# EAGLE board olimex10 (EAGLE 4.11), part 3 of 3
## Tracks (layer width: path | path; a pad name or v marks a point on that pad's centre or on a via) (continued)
N$64 (continued)
  Top 0.254: IC2.1 40.64,135.89 39.37,134.62 39.37,130.81 40.64,129.54 47.62,129.54 47.62,131.44 SW2.13
N$65
  Top 0.254: SW2.11 49.53,135.89 49.53,138.43 45.72,142.24 IC2.14
N$66
  Top 0.254: SW2.10 57.78,130.18 59.69,130.18 59.69,133.35 57.15,135.89 57.15,138.43 52.07,143.51 52.07,146.69 49.53,149.22 48.26,149.22 IC2.13
N$67
  Top 0.254: SW2.9 54.61,135.89 54.61,139.7 50.8,143.51 IC2.12
N$68
  Top 0.254: SW3.16 70.48,130.18 74.93,130.18 74.93,133.35 76.2,134.62 IC3.4
N$69
  Top 0.254: SW3.15 71.12,133.35 73.66,135.89 IC3.3
N$70
  Top 0.254: SW3.14 73.66,133.35 74.93,134.62 74.93,138.43 74.3,139.06 71.12,139.06 IC3.2
N$71
  Top 0.254: IC3.1 68.58,135.89 67.31,134.62 67.31,130.81 68.58,129.54 75.56,129.54 75.56,131.44 SW3.13
N$72
  Top 0.254: SW3.11 81.28,133.35 82.55,134.62 82.55,146.05 78.74,149.86 69.85,149.86 69.85,143.51 70.48,142.88 73.03,142.88 73.03,144.15 IC3.14
N$73
  Top 0.254: SW3.10 81.92,130.18 77.47,130.18 77.47,142.24 76.2,143.51 IC3.13
N$74  (via drill 0.61)
  Top 0.254: v87.63,142.24 87.63,134.62 86.36,133.35 SW3.9
  Bottom 0.254: v87.63,142.24 87,142.88 80.64,142.88 IC3.12
N$75
  Top 0.254: SW4.16 98.42,130.18 102.87,130.18 102.87,133.35 104.14,134.62 IC4.4
N$76
  Top 0.254: SW4.15 99.06,133.35 101.6,135.89 IC4.3
N$77
  Top 0.254: SW4.14 101.6,133.35 102.87,134.62 102.87,138.43 102.23,139.06 99.06,139.06 IC4.2
N$78
  Top 0.254: IC4.1 96.52,135.89 95.25,134.62 95.25,130.81 96.52,129.54 103.5,129.54 103.5,131.44 SW4.13
N$79  (via drill 0.61)
  Top 0.254: v97.79,133.99 97.79,139.7 101.6,143.51 IC4.14
  Bottom 0.254: v97.79,133.99 107.31,133.99 SW4.11
N$80
  Top 0.254: SW4.10 108.58,135.25 105.41,135.25 105.41,142.24 104.14,143.51 IC4.13
N$81
  Top 0.254: SW4.9 110.49,135.89 110.49,139.7 106.68,143.51 IC4.12
N$82
  Top 0.254: SW4.12 106.68,130.81 103.5,127.64 94.61,127.64 94.61,137.16 95.25,137.79 95.25,139.7 99.06,143.51 IC4.15
N$83
  Top 0.254: SW3.12 78.74,133.35 80.01,134.62 80.01,146.69 77.47,149.22 71.12,149.22 IC3.15
N$84
  Top 0.254: SW2.12 50.8,130.81 47.62,127.64 38.73,127.64 38.73,137.16 39.37,137.79 39.37,139.7 43.18,143.51 IC2.15
N$85
  Top 0.254: R16.1 246.38,191.13 247.65,192.41 248.92,192.41 DEA0.A
N$86
  Bottom 0.254: R17.1 8.26,182.88 10.79,180.34 DMA00.A
N$87
  Bottom 0.254: R18.1 23.5,182.88 26.04,180.34 DMA01.A
N$88
  Bottom 0.254: R19.1 38.73,182.88 41.27,180.34 DMA02.A
N$89
  Bottom 0.254: R20.1 76.83,182.88 79.38,180.34 DMA03.A
N$90
  Bottom 0.254: R21.1 92.08,182.88 94.61,180.34 DMA04.A
N$91
  Bottom 0.254: R22.1 107.31,182.88 109.86,180.34 DMA05.A
N$92
  Bottom 0.254: R23.1 145.41,182.88 147.96,180.34 DMA06.A
N$93
  Bottom 0.254: R24.1 160.66,182.88 163.19,180.34 DMA07.A
N$94
  Bottom 0.254: R25.1 175.9,182.88 178.44,180.34 DMA08.A
N$95
  Bottom 0.254: R26.1 214,182.88 216.53,180.34 DMA09.A
N$96
  Top 0.254: R27.1 229.24,182.88 231.78,180.34 DMA10.A
N$97  (via drill 0.61)
  Top 0.254: v246.38,180.34 246.38,180.97 244.47,182.88 R28.1
  Bottom 0.254: v246.38,180.34 DMA11.A
N$98
  Bottom 0.254: R29.1 8.26,170.18 10.79,172.72 DMB00.A
N$99
  Bottom 0.254: R30.1 23.5,170.18 26.04,172.72 DMB01.A
N$100
  Bottom 0.254: R31.1 38.73,170.18 41.27,172.72 DMB02.A
N$101
  Bottom 0.254: R32.1 76.83,170.18 79.38,172.72 DMB03.A
N$102
  Bottom 0.254: R33.1 92.08,170.18 94.61,172.72 DMB04.A
N$103
  Bottom 0.254: R34.1 107.31,170.18 109.86,172.72 DMB05.A
N$104
  Bottom 0.254: R35.1 145.41,170.18 147.96,172.72 DMB06.A
N$105
  Bottom 0.254: R36.1 160.66,170.18 163.19,172.72 DMB07.A
N$106
  Bottom 0.254: R37.1 175.9,170.18 178.44,172.72 DMB08.A
N$107
  Bottom 0.254: R38.1 214,170.18 216.53,172.72 DMB09.A
N$108
  Bottom 0.254: R39.1 229.24,170.18 231.78,172.72 DMB10.A
N$109  (via drill 0.61)
  Top 0.254: R40.1 v243.84,172.72
  Bottom 0.254: v243.84,172.72 DMB11.A
N$110
  Top 0.254: CIE.A 12.7,165.74 10.16,168.28 R41.1
N$111
  Top 0.254: EIE.A 27.94,165.74 25.4,168.28 R42.1
N$112
  Top 0.254: PIE.A 43.18,165.74 40.64,168.28 R43.1
N$113
  Top 0.254: DRE.A 81.28,165.74 78.74,168.28 R44.1
N$114
  Top 0.254: R/W.A 96.52,165.74 93.98,168.28 R45.1
N$115
  Top 0.254: DBR.A 111.76,165.74 109.22,168.28 R46.1
N$116
  Top 0.254: DRL.A 149.86,165.74 147.32,168.28 R47.1
N$117
  Top 0.254: WLS.A 165.1,165.74 162.56,168.28 R48.1
N$118
  Top 0.254: NXD.A 180.34,165.74 177.8,168.28 R49.1
N$119
  Top 0.254: WCO.A 218.44,165.74 215.9,168.28 R50.1
N$120
  Top 0.254: PER.A 233.68,165.74 231.14,168.28 R51.1
N$121  (via drill 0.61)
  Top 0.254: DCF.A v248.92,169.54
  Bottom 0.254: v248.92,169.54 248.28,170.18 R52.1
N$122
  Bottom 0.254: F.3.K 15.24,181.61 14.61,181.61 13.97,180.97 13.97,178.44 56.52,178.44 IC47.2
N$123  (via drill 0.61)
  Top 0.254: v34.29,184.78 31.11,187.96 F.2.K
  Bottom 0.254: v34.29,184.78 34.92,184.15 59.69,184.15 IC47.4
N$124
  Bottom 0.254: F.1.K 46.35,187.96 48.26,189.87 71.75,189.87 72.39,189.23 72.39,182.25 70.48,182.25 IC47.6
N$125
  Bottom 0.254: DMA00.K 15.88,180.34 21.59,186.06 69.22,186.06 IC47.8
N$126
  Top 0.254: DMA01.K 31.11,180.34 43.18,192.41 66.04,192.41 IC47.10
N$127
  Top 0.254: DMA02.K 45.72,180.97 55.24,190.5 57.15,190.5 57.15,186.69 57.78,186.06 60.33,186.06 60.33,187.32 IC47.12
N$128
  Bottom 0.254: IC48.2 56.52,167 34.29,167 31.11,163.83 24.77,163.83 15.88,172.72 DMB00.K
N$129
  Top 0.254: DMB01.K 31.11,172.72 41.27,162.56 69.85,162.56 69.85,166.37 69.22,167 63.5,167 IC48.4
N$130
  Top 0.254: G2.+@1 G2.+ 292.74,18.41 292.74,19.05 G2.+@3 G2.+@4 | G2.+@4 G2.+@2 | D3.A 293.37,12.7 G2.+@4
N$131
  Top 0.254: G1.+@1 G1.+ 292.74,48.9 292.74,49.53 G1.+@3 G1.+@4 | G1.+@4 G1.+@2 | D2.A 293.37,43.18 G1.+@4
N$132
  Top 0.254: DMB02.K 45.72,172.09 44.45,170.81 44.45,164.47 45.72,163.19 67.94,163.19 67.94,164.47 IC48.6
N$133
  Bottom 0.254: CIE.K 15.24,171.45 14.61,171.45 13.97,172.09 13.97,174.62 69.22,174.62 IC48.8
N$134
  Bottom 0.254: EIE.K 31.11,165.1 34.92,168.91 62.23,168.91 IC48.10
N$135
  Top 0.254: PIE.K 54.61,165.1 54.61,166.37 IC48.12
N$136
  Bottom 0.254: DEA7.K 99.69,187.96 103.5,184.15 129.54,184.15 IC49.4
N$137  (via drill 0.61)
  Top 0.254: v132.72,186.06 IC49.6
  Bottom 0.254: v132.72,186.06 116.84,186.06 114.94,187.96 DEA6.K
N$138  (via drill 0.61)
  Top 0.254: v136.53,184.78 139.7,187.96 IC49.8
  Bottom 0.254: v136.53,184.78 113.03,184.78 108.58,189.23 78.11,189.23 78.11,186.69 83.82,180.97 DMA03.K
N$139  (via drill 0.61)
  Top 0.254: v109.22,189.87 99.69,180.34 DMA04.K
  Bottom 0.254: v109.22,189.87 110.49,191.13 132.72,191.13 IC49.10
N$140
  Top 0.254: DMA05.K 114.3,180.97 123.19,189.87 123.19,190.5 128.27,195.58 129.54,195.58 IC49.12
N$141  (via drill 0.61)
  Top 0.254: v125.73,174.62 125.73,167.64 127,166.37 IC50.2
  Bottom 0.254: v125.73,174.62 86.36,174.62 84.45,172.72 DMB03.K
N$142  (via drill 0.61)
  Top 0.254: v105.41,161.93 105.41,165.74 99.06,172.09 DMB04.K | v132.08,161.93 IC50.4
  Bottom 0.254: v105.41,161.93 v132.08,161.93
N$143  (via drill 0.61)
  Top 0.254: v118.11,169.54 114.94,172.72 DMB05.K | v135.89,169.54 135.89,168.91 137.16,167.64 IC50.6
  Bottom 0.254: v118.11,169.54 v135.89,169.54
N$144  (via drill 0.61)
  Top 0.254: v100.33,169.54 100.33,167 99.06,165.74 R/W.K
  Bottom 0.254: v100.33,169.54 100.97,168.91 114.94,168.91 117.47,171.45 123.19,171.45 123.83,170.81 132.72,170.81 IC50.10
N$145  (via drill 0.61)
  Top 0.254: v129.54,168.28 IC50.12
  Bottom 0.254: v129.54,168.28 118.11,168.28 114.94,165.1 DBR.K
N$146  (via drill 0.61)
  Top 0.254: v156.84,184.15 153.03,187.96 DEA5.K
  Bottom 0.254: v156.84,184.15 180.34,184.15 182.88,181.61 191.77,181.61 192.41,182.25 193.68,182.25 IC51.2
N$147  (via drill 0.61)
  Top 0.254: v173.99,175.9 173.99,180.97 167.64,187.32 DEA4.K | v200.03,175.9 200.66,176.53 IC51.4
  Bottom 0.254: v173.99,175.9 174.62,176.53 198.75,176.53 199.39,175.9 v200.03,175.9
N$148  (via drill 0.61)
  Top 0.254: v203.2,184.15 205.74,181.61 IC51.6
  Bottom 0.254: v203.2,184.15 202.56,184.78 198.12,184.78 197.49,184.15 187.32,184.15 183.51,187.96 DEA3.K
N$149  (via drill 0.61)
  Top 0.254: v190.5,179.07 191.13,179.71 v191.13,186.06
  Bottom 0.254: v190.5,179.07 154.31,179.07 153.03,180.34 DMA06.K | v191.13,186.06 206.38,186.06 IC51.8
N$150  (via drill 0.61)
  Top 0.254: v172.09,194.31 166.37,188.59 166.37,182.25 167.64,180.97 DMA07.K | v199.39,194.94 199.39,186.69 200.03,186.06 202.56,186.06 202.56,187.32 IC51.10
  Bottom 0.254: v172.09,194.31 173.35,195.58 198.75,195.58 v199.39,194.94
N$151  (via drill 0.61)
  Top 0.254: v184.78,183.51 184.78,182.88 182.88,180.97 DMA08.K | v198.12,183.51 IC51.12
  Bottom 0.254: v184.78,183.51 v198.12,183.51
N$152  (via drill 0.61)
  Top 0.254: v158.12,177.8 153.03,172.72 DMB06.K | v194.31,178.44 194.31,167.64 195.58,166.37 IC52.2
  Bottom 0.254: v158.12,177.8 193.68,177.8 v194.31,178.44
N$153  (via drill 0.61)
  Top 0.254: v177.16,163.83 168.28,172.72 DMB07.K
  Bottom 0.254: v177.16,163.83 177.8,163.19 198.75,163.19 IC52.4
N$154  (via drill 0.61)
  Top 0.254: v205.74,169.54 IC52.6
  Bottom 0.254: v205.74,169.54 187.32,169.54 183.51,172.72 DMB08.K
N$155  (via drill 0.61)
  Top 0.254: v169.54,170.18 169.54,167.64 167.64,165.74 WLS.K
  Bottom 0.254: v169.54,170.18 175.26,175.9 198.12,175.9 199.39,174.62 201.29,174.62 IC52.10
N$156  (via drill 0.61)
  Top 0.254: v187.32,173.99 187.32,170.18 182.88,165.74 NXD.K
  Bottom 0.254: v187.32,173.99 188.59,175.26 196.85,175.26 198.12,173.99 IC52.12
N$157  (via drill 0.61)
  Top 0.254: v222.88,182.88 222.88,185.42 220.98,187.32 DEA2.K
  Bottom 0.254: v222.88,182.88 224.16,181.61 257.18,181.61 257.81,180.97 259.71,180.97 260.99,182.25 262.25,182.25 IC53.2
N$158  (via drill 0.61)
  Top 0.254: v262.89,186.06 264.8,184.15 264.8,182.25 265.43,181.61 265.43,179.07 266.06,178.44 268.61,178.44 268.61,179.71 IC53.4
  Bottom 0.254: v262.89,186.06 260.99,186.06 259.71,187.32 258.44,187.32 257.81,186.69 238.12,186.69 236.85,187.96 DEA1.K
N$159  (via drill 0.61)
  Top 0.254: v257.81,182.25 252.09,187.96 DEA0.K
  Bottom 0.254: v257.81,182.25 258.44,182.88 265.43,182.88 266.06,182.25 272.42,182.25 IC53.6
N$160
  Top 0.254: DMA09.K 221.62,180.34 235.59,194.31 276.86,194.31 IC53.8
N$161  (via drill 0.61)
  Top 0.254: v236.85,184.78 236.85,181.61 236.22,180.97 DMA10.K | v258.44,186.06 260.35,187.96 260.35,189.23 263.52,192.41 271.78,192.41 IC53.10
  Bottom 0.254: v236.85,184.78 238.12,186.06 v258.44,186.06
N$162  (via drill 0.61)
  Top 0.254: v255.27,183.51 252.09,180.34 DMA11.K | v266.06,183.51 266.7,184.15 IC53.12
  Bottom 0.254: v255.27,183.51 v266.06,183.51
N$163
  Top 0.254: DMB09.K 226.69,172.72 227.33,172.09 234.31,179.07 237.49,179.07 237.49,183.51 238.76,184.78 241.3,184.78 241.3,170.18 240.66,169.54 240.66,149.86 243.21,147.32 243.21,144.15 265.43,144.15 265.43,162.56 264.16,163.83 IC54.2
N$164  (via drill 0.61)
  Top 0.254: v258.44,172.09 259.08,171.45 v259.08,166.37
  Bottom 0.254: v258.44,172.09 257.81,171.45 238.12,171.45 236.85,172.72 DMB10.K | v259.08,166.37 259.71,167 267.33,167 IC54.4
N$165  (via drill 0.61)
  Top 0.254: v252.73,169.54 252.73,170.81 251.46,172.09 DMB11.K | v273.69,169.54 274.32,168.91 IC54.6
  Bottom 0.254: v252.73,169.54 v273.69,169.54
N$166  (via drill 0.61)
  Top 0.254: v241.94,146.69 240.03,148.59 240.03,170.18 240.66,170.81 240.66,184.15 239.4,184.15 238.12,182.88 238.12,178.44 234.95,178.44 221.62,165.1 WCO.K | v274.32,147.32 275.59,148.59 275.59,169.54 276.86,170.81 IC54.8
  Bottom 0.254: v241.94,146.69 242.57,147.32 v274.32,147.32
N$167
  Top 0.254: PER.K 236.22,148.59 241.3,143.51 273.05,143.51 273.05,168.91 271.78,170.18 IC54.10
N$168  (via drill 0.61)
  Top 0.254: DCF.K v251.46,168.28
  Bottom 0.254: v251.46,168.28 273.69,168.28 274.95,169.54 274.95,170.18 274.32,170.18 273.69,170.81 268.61,170.81 IC54.12
N$169
  Top 0.254: PAD10.1 DRE.K
N$170
  Top 0.254: PAD11.1 DRL.K
N$171
  Bottom 0.254: DEA8.K 84.45,187.96 93.34,179.07 124.46,179.07 IC49.2
NXD  (via drill 0.61)  (1 unrouted)
  Top 0.254: v207.65,53.34 207.01,52.7 v207.01,6.99 | v118.75,4.45 116.84,6.35 IC23.5 | v190.5,161.29 190.5,170.81 v189.87,171.45 | v226.06,161.93 227.97,163.83 234.95,163.83 234.95,165.74 235.59,166.37 238.76,166.37 238.76,153.67 v238.12,153.03
  Bottom 0.254: IC23.5 114.3,10.16 74.93,10.16 74.3,10.79 53.98,10.79 52.07,8.89 34.92,8.89 33.66,7.62 SV1.17 | v207.01,6.99 205.74,5.71 153.67,5.71 153.03,6.35 137.16,6.35 135.89,5.08 119.38,5.08 v118.75,4.45 | v207.65,53.34 IC30.4 | v189.87,171.45 190.5,170.81 193.68,170.81 IC52.13 | v190.5,161.29 191.13,161.93 209.55,161.93 210.19,161.29 211.46,161.29 212.09,161.93 v226.06,161.93 | v238.12,153.03 241.94,149.22 262.25,149.22 263.52,151.13 SV3.17
NXD\  (via drill 0.61)
  Top 0.254: v134.62,71.75 134.62,65.41 130.18,60.96 130.18,52.7 129.54,52.07 129.54,39.37 130.18,38.73 130.18,24.13 127.64,21.59 127.64,5.08 121.92,5.08 IC23.6 | v146.05,73.03 147.32,74.3 147.32,109.22 148.59,110.49 148.59,135.89 150.5,137.79 150.5,140.34 v153.03,142.88
  Bottom 0.254: v134.62,71.75 135.89,73.03 v146.05,73.03 | v153.03,142.88 153.67,142.24 161.29,142.24 161.93,142.88 210.82,142.88 225.43,128.27 225.43,107.31 219.07,107.31 IC12.12
PBIT  (via drill 0.61)
  Top 0.254: v61.59,90.17 60.96,89.53 60.96,43.81 62.23,42.55 62.23,24.13 67.31,24.13 IC35.11 | v58.42,93.34 57.15,94.61 57.15,109.22 58.42,110.49 IC14.6
  Bottom 0.254: v61.59,90.17 v58.42,93.34
PCA
  Bottom 0.254: IC55.5 151.13,12.7 152.4,13.97 179.07,13.97 180.34,12.7 IC37.8 212.09,12.7 213.36,11.43 224.16,11.43 224.16,95.89 219.71,100.33 217.17,100.33 IC12.3
PER  (via drill 0.61)  (1 unrouted)
  Top 0.254: v204.47,64.77 204.47,129.54 203.2,130.81 203.2,138.43 191.13,150.5 143.51,150.5 143.51,134.62 142.24,133.35 IC9.9 | v34.29,31.75 34.29,23.5 36.83,20.95 36.83,9.53 38.1,8.26 SV1.21 | v166.37,37.47 168.91,34.92 v168.91,33.66 | IC54.11 269.24,171.45 267.97,170.18 267.97,153.03 269.24,151.76 SV3.21
  Bottom 0.254: v204.47,64.77 IC30.2 211.46,57.78 216.53,57.78 217.17,57.15 220.98,57.15 220.98,38.1 217.17,34.29 169.54,34.29 v168.91,33.66 | v34.29,31.75 36.83,34.29 127.64,34.29 129.54,36.2 149.86,36.2 151.13,37.47 v166.37,37.47
PER\  (via drill 0.61)
  Top 0.254: v146.05,102.87 146.05,129.54 144.78,130.81 IC9.8 | v157.48,102.87 160.02,105.41 v160.02,107.31
  Bottom 0.254: v157.48,102.87 v146.05,102.87 | v160.02,107.31 206.38,107.31 209.55,104.14 IC12.4
PIE  (via drill 0.61)  (1 unrouted)
  Top 0.254: v186.06,4.45 190.5,8.89 INTENB.2 | v153.03,5.08 151.76,6.35 | 151.76,6.35 151.76,13.34 IC55.4 | v221.62,8.26 221.62,50.16 IC30.17 | 151.76,6.35 151.76,1.91 101.6,1.91 98.42,5.08 98.42,9.53 93.34,9.53 92.71,8.89 92.71,1.91 24.13,1.91 18.41,7.62 SV1.5 | v62.23,178.44 62.23,177.8 58.42,173.99 IC48.13 | v158.75,175.9 166.37,168.28 166.37,164.47 174.62,156.21 234.31,156.21 v234.31,158.75 | v241.94,158.75 v241.94,154.94
  Bottom 0.254: v153.03,5.08 185.42,5.08 v186.06,4.45 217.81,4.45 v221.62,8.26 | v62.23,178.44 62.87,177.8 149.86,177.8 150.5,178.44 151.76,178.44 152.4,177.8 156.84,177.8 v158.75,175.9 | v234.31,158.75 v241.94,158.75 | v241.94,154.94 241.94,152.4 247.01,152.4 248.28,151.13 SV3.5
PROTECT  (via drill 0.61)
  Top 0.254: IC5.6 v142.24,140.97 | v162.56,140.97 IC6.3
  Bottom 0.254: v142.24,140.97 v162.56,140.97
SETNXD\
  Top 0.254: IC23.4 112.39,5.71 99.06,5.71 99.06,17.14 91.44,24.77 91.44,43.18 92.08,43.81 92.08,94.61 92.71,95.25 92.71,99.69 91.44,100.97 IC21.9
SETPER\
  Bottom 0.254: IC13.5 25.4,114.3 22.86,114.3 19.05,118.11 19.05,122.56 12.06,122.56 11.43,123.19 11.43,129.54 137.16,129.54 IC9.10
SETWLS\  (via drill 0.61)
  Top 0.254: v139.7,128.27 137.16,125.73 IC9.4 | v171.45,130.18 171.45,134.62 172.72,135.89 IC6.7
  Bottom 0.254: v139.7,128.27 140.97,129.54 160.02,129.54 160.66,130.18 v171.45,130.18
SKIP\  (via drill 0.61)
  Top 0.254: IC19.6 198.12,90.17 195.58,92.71 IC19.10 v195.58,104.14 | v132.08,104.78 IC17.2
  Bottom 0.254: R1.1 183.51,86.36 184.15,87 186.06,87 IC19.2 189.87,87 196.22,87 IC19.6 | v132.08,104.78 144.15,104.78 144.78,105.41 169.54,105.41 170.81,104.14 v195.58,104.14
START\  (via drill 0.61)
  Top 0.254: 144.15,45.09 144.15,14.61 DMA0-3.11 | 144.15,45.09 DMA4-7.11 | 144.15,45.09 144.15,79.38 DMA8-11.11 | v146.05,99.69 v146.05,81.28 | v162.56,100.33 IC18.3
  Bottom 0.254: v162.56,100.33 149.86,100.33 148.59,99.06 146.69,99.06 v146.05,99.69 | v146.05,81.28 DMA8-11.11
VCC  (via drill 0.61)  (3 unrouted)
  Top 0.508: J7.2 193.04,41.27 191.13,43.18 191.13,45.72 193.04,47.62 J5.2 J4.2 J3.2 | 187.96,29.21 v187.96,40.64 | 187.96,29.21 INTENB.16 | IC31.20 171.45,66.04 C31.1 | IC38.20 171.45,31.75 C38.1 | IC55.14 156.21,24.13 C40.1 156.21,26.04 155.57,26.67 v155.57,27.94 | 139.7,60.33 v139.06,59.69 | 139.7,60.33 139.7,61.59 140.34,62.23 C39.1 | 139.7,60.33 139.7,40.64 140.34,40.01 140.34,29.21 140.97,28.57 C46.1 | v186.69,29.21 187.96,29.21 | IC37.20 217.17,31.75 C37.1 | IC30.20 217.17,62.23 C30.1 216.53,63.5 216.53,87 FIELD.16 217.17,90.17 C44.1 217.17,92.08 216.53,92.71 216.53,109.86 IC12.14 217.17,113.03 C12.1 | IC17.16 129.54,120.65 128.27,121.92 128.27,128.91 127,130.18 C9.1 127,131.44 125.73,132.72 125.73,141.6 127,142.88 C5.1 | 153.67,128.91 154.94,130.18 C10.1 | 153.67,128.91 152.4,127.64 152.4,121.28 154.94,118.75 C18.1 154.94,117.47 155.57,116.84 155.57,114.3 156.21,113.67 C27.1 156.21,95.25 DAR8-11.16 154.94,91.44 154.94,64.14 156.21,62.87 C42.1 | 153.67,128.91 153.67,141.6 154.94,142.88 C6.1 | DMA8-11.16 140.97,95.25 C8.1 | IC24.20 171.45,100.33 C24.1 | IC19.14 C19.1 | IC11.4 193.04,113.03 195.58,115.57 IC11.10 | 181.61,120.02 181.61,128.91 180.34,130.18 C7.1 | 181.61,120.02 182.88,118.75 C11.1 | RA.1 RL.1 208.28,121.92 IC8.4 206.38,128.91 206.38,138.43 C45.+ | C48.1 220.98,130.18 219.71,131.44 219.71,132.08 IC8.8 | 181.61,120.02 181.61,98.42 182.88,97.16 R1.2 | 49.53,109.22 45.72,105.41 IC33.16 | 50.16,109.86 49.53,109.22 | 50.16,109.86 50.8,110.49 IC14.3 | 49.53,109.22 49.53,121.28 47.62,121.28 IC14.14 | 36.83,140.97 36.83,125.73 43.18,119.38 C14.1 | 36.83,140.97 36.83,141.6 38.1,142.88 C2.1
  Top 0.508: IC20.20 12.7,105.41 13.34,106.05 13.34,115.57 15.24,117.47 C13.1 | 36.83,140.97 v36.2,140.97 | 80.01,120.65 80.01,114.3 78.74,113.03 IC15.3 | 80.01,120.65 79.38,121.28 73.66,121.28 IC15.14 | v73.66,107.31 IC21.16 | IC16.16 99.06,118.11 100.33,116.84 100.33,106.68 101.6,105.41 IC22.14 | 92.71,125.09 92.71,141.6 93.98,142.88 C4.1 | 92.71,125.09 96.52,121.28 C16.1 | 80.01,120.65 81.92,122.56 91.44,122.56 91.44,123.83 92.71,125.09 | IC34.20 29.21,41.91 C34.1 | v43.18,15.88 SV1.26 SV1.25 | v33.66,40.64 33.02,40.01 33.02,20.95 35.56,18.41 R2.2 | IC28.20 73.03,74.3 73.03,74.93 72.39,75.56 C28.1 72.39,76.83 73.66,78.11 v73.66,80.01 | C26.1 29.21,75.56 29.84,74.93 29.84,74.3 IC26.20 | v40.64,73.66 RS08.2 | 92.71,62.87 92.71,51.44 93.98,50.16 C32.1 93.98,48.9 92.71,47.62 92.71,42.55 96.52,38.73 IC36.16 | 92.71,62.87 93.98,64.14 C29.1 | 92.71,62.87 92.71,78.11 93.98,79.38 C25.1 | IC35.20 72.39,41.91 C35.1 | IC36.6 109.22,21.59 106.68,19.05 IC23.14 | v79.38,40.64 78.74,40.01 IC41.16 | v74.3,9.53 76.2,11.43 C41.1 | C22.1 99.06,102.23 96.52,99.69 IC25.16 | 50.16,109.86 51.44,108.58 v51.44,107.95 | v99.69,147.96 IC4.16 | D1.A 236.22,57.15 237.49,58.42 RF08A.2 | D6.A 238.12,123.83 238.12,124.46 RF08B.2 | 260.35,184.78 260.35,185.42 261.62,186.69 IC53.14 | 260.35,184.78 260.35,175.26 261.62,173.99 IC54.14 261.62,171.45 260.35,170.18 v260.35,160.02 | R28.2 R16.2 249.56,193.04 256.54,186.06 256.54,184.78 260.35,184.78 | R26.2 R14.2 R27.2 R15.2 | SV3.26 SV3.25 | R50.2 R38.2 212.72,160.02 211.46,158.75 200.66,158.75 v200.66,160.66 | R39.2 R51.2 | IC48.14 55.88,173.99 54.61,175.26 54.61,185.42 55.88,186.69 IC47.14
  Top 0.508: R7.2 R19.2 R6.2 R18.2 R5.2 8.89,193.04 | 8.89,193.04 R17.2 | 8.89,193.04 8.89,161.93 7.62,160.66 R29.2 R41.2 R30.2 R42.2 R31.2 R43.2 R32.2 | 123.19,181.61 123.19,186.69 124.46,187.96 IC49.14 | 123.19,181.61 123.19,175.26 124.46,173.99 IC50.14 | 107.95,160.02 R34.2 R45.2 R33.2 90.81,160.02 90.81,158.12 83.82,158.12 81.92,160.02 R44.2 | 107.95,160.02 R46.2 | 123.19,181.61 116.2,181.61 116.2,179.07 107.95,170.81 107.95,160.02 | R37.2 R49.2 177.8,160.66 181.61,164.47 181.61,191.13 | R35.2 R47.2 150.5,160.02 152.4,158.12 159.38,158.12 159.38,160.02 R36.2 R48.2 | R10.2 R22.2 R9.2 R21.2 R8.2 R20.2 | IC52.14 193.04,173.99 191.77,175.26 191.77,184.78 193.04,186.06 IC51.14 192.41,188.59 184.15,188.59 181.61,191.13 | R12.2 R24.2 R11.2 | 181.61,191.13 179.71,193.04 R13.2
  Bottom 0.508: C43.1 186.06,16.51 186.69,17.14 187.32,17.14 INTENB.16 | v187.96,40.64 J7.2 | DMA0-3.16 142.24,26.04 140.97,27.3 C46.1 v155.57,27.94 156.84,29.21 170.18,29.21 | 154.31,63.5 142.88,63.5 141.6,62.23 C39.1 | 154.31,63.5 155.57,62.23 C42.1 156.21,61.59 156.84,61.59 156.84,60.33 DAR4-7.16 | v139.06,59.69 DMA4-7.16 | 170.18,29.21 171.45,30.48 IC38.20 | 154.31,63.5 166.37,63.5 167,64.14 170.81,64.14 171.45,64.77 IC31.20 | 170.18,29.21 v186.69,29.21 | C37.1 217.81,33.02 221.62,36.83 221.62,60.33 219.07,60.33 IC30.20 | C17.1 127.64,118.11 128.27,118.75 128.91,118.75 IC17.16 | C9.1 127.64,130.81 128.27,131.44 128.91,131.44 IC9.14 | IC6.16 156.84,144.15 156.21,144.15 155.57,143.51 C6.1 154.94,144.15 152.4,144.15 151.13,142.88 131.44,142.88 IC5.14 128.91,144.15 128.27,144.15 127.64,143.51 C5.1 118.11,143.51 113.67,147.96 v99.69,147.96 | C18.1 155.57,118.11 156.21,118.75 156.84,118.75 IC18.14 | C10.1 155.57,130.81 156.21,131.44 156.84,131.44 IC10.14 | C8.1 141.6,96.52 142.24,95.89 149.86,95.89 150.5,95.25 153.03,95.25 154.31,96.52 C27.1 156.84,96.52 158.12,97.79 170.18,97.79 171.45,99.06 IC24.20 173.99,99.06 176.53,96.52 R1.2 IC19.14 | C7.1 180.97,130.81 181.61,131.44 182.25,131.44 IC7.16 | C11.1 183.51,118.11 184.15,118.75 184.78,118.75 IC11.14 187.32,121.28 193.68,121.28 IC11.10 197.49,117.47 213.36,117.47 | 213.36,117.47 211.46,119.38 RA.1 | 213.36,117.47 216.53,114.3 C12.1 | IC8.8 217.17,132.08 210.19,139.06 207.01,139.06 C45.+ | C2.1 38.73,143.51 39.37,144.15 40.01,144.15 IC2.16 | C14.1 43.81,118.11 44.45,118.75 45.09,118.75 IC14.14 | C33.1 43.81,102.87 44.45,103.5 45.09,103.5 IC33.16
  Bottom 0.508: IC3.16 67.94,144.15 67.31,144.15 66.67,143.51 C3.1 65.41,143.51 63.5,141.6 36.2,141.6 | IC1.16 12.06,144.15 11.43,144.15 10.79,143.51 C1.1 10.16,142.88 8.89,141.6 | C20.1 10.79,102.87 11.43,103.5 12.06,103.5 IC20.20 | IC13.3 22.86,113.03 17.78,118.11 IC13.14 17.14,118.75 16.51,118.75 15.88,118.11 C13.1 15.24,118.75 6.99,118.75 6.99,139.7 8.89,141.6 | 36.2,141.6 8.89,141.6 | v36.2,140.97 36.2,141.6 | C15.1 71.75,118.11 72.39,118.75 73.03,118.75 IC15.14 | C4.1 94.61,143.51 95.25,144.15 95.89,144.15 IC4.16 | C16.1 97.16,118.11 97.79,118.75 98.42,118.75 IC16.16 | C21.1 71.75,102.87 72.39,103.5 73.03,103.5 IC21.16 | IC22.14 100.97,103.5 100.33,103.5 99.69,102.87 C22.1 98.42,102.87 95.25,106.05 86.36,106.05 85.09,107.31 v73.66,107.31 73.03,106.68 52.7,106.68 v51.44,107.95 | v43.18,15.88 38.1,15.88 36.2,17.78 R2.2 | v33.66,40.64 IC34.20 | IC26.20 v40.64,73.66 | C28.1 71.75,76.2 70.48,74.93 64.77,74.93 63.5,76.2 C26.1 | IC25.16 95.89,80.64 95.25,80.64 94.61,80.01 C25.1 v73.66,80.01 | C32.1 94.61,49.53 95.25,50.16 95.89,50.16 IC32.16 | C29.1 94.61,64.77 95.25,65.41 95.89,65.41 IC29.16 | C36.1 94.61,29.21 95.25,29.84 95.89,29.84 IC36.16 102.87,24.13 102.87,20.95 107.31,20.95 IC36.6 | C41.1 76.83,13.97 77.47,14.61 78.11,14.61 IC41.16 80.64,17.14 100.33,17.14 103.5,13.97 C23.1 104.78,13.97 105.41,14.61 106.05,14.61 IC23.14 | v79.38,40.64 IC35.20 | v74.3,9.53 73.03,8.26 44.45,8.26 43.81,7.62 SV1.25 | R28.2 R15.2 | R50.2 R39.2 | R51.2 R40.2 R52.2 v260.35,160.02 267.33,160.02 273.69,153.67 SV3.26 | IC47.14 54.61,186.69 42.55,186.69 40.64,188.59 R7.2 | R44.2 R32.2 | R48.2 R37.2
  Bottom 0.508: R13.2 R25.2 168.91,193.04 168.28,193.68 162.56,193.68 R12.2 | R11.2 R23.2 R10.2 | R46.2 R35.2 | v200.66,160.66 200.03,161.29 192.41,161.29 191.13,160.02 R49.2
WE\  (via drill 0.61)  (2 unrouted)
  Top 0.254: v112.39,100.33 112.39,98.42 111.76,97.79 IC22.5 111.76,90.17 v110.49,88.9 | v148.59,100.33 151.76,103.5 v151.76,139.7 | v42.55,68.58 42.55,66.04 40.64,64.14 RS08.8 | v53.98,70.48 54.61,71.12 v54.61,87.63 | IC43.29 246.38,27.3 245.11,28.57 245.11,31.75 246.38,33.02 IC42.29 246.38,52.7 245.11,53.98 245.11,57.78 245.75,58.42 RF08A.8 | IC45.29 246.38,87.63 245.11,88.9 245.11,97.79 245.75,98.42 245.75,111.12 IC39.29 246.38,113.03 245.11,114.3 245.11,122.56 246.38,123.83 RF08B.8
  Bottom 0.254: v112.39,100.33 113.03,99.69 123.83,99.69 125.09,100.97 147.96,100.97 v148.59,100.33 | v151.76,139.7 152.4,140.34 161.93,140.34 163.19,139.06 165.74,139.06 IC6.5 | v42.55,68.58 44.45,70.48 v53.98,70.48 | v54.61,87.63 97.79,87.63 99.06,88.9 v110.49,88.9
WLS  (via drill 0.61)  (1 unrouted)
  Top 0.254: v140.97,148.59 140.97,127 139.7,125.73 IC9.5 | v204.47,144.15 213.36,135.25 213.36,25.4 IC37.4 | v216.53,165.1 210.82,159.38 208.28,159.38 204.47,163.19 204.47,167.64 200.66,171.45 IC52.11 | v258.44,164.47 259.08,163.83 259.08,155.57 260.35,154.31 260.35,153.03 261.62,151.76 SV3.15
  Bottom 0.254: v204.47,144.15 198.75,149.86 142.24,149.86 v140.97,148.59 139.06,150.5 15.88,150.5 10.79,145.41 2.54,145.41 2.54,15.88 12.06,6.35 28.57,6.35 29.84,7.62 SV1.15 | v216.53,165.1 217.81,163.83 257.81,163.83 v258.44,164.47
WLS\  (via drill 0.61)
  Top 0.254: IC9.6 v142.24,128.27
  Bottom 0.254: v142.24,128.27 142.88,128.91 160.66,128.91 161.29,129.54 170.81,129.54 171.45,128.91 196.22,128.91 199.39,125.73 199.39,121.28 209.55,121.28 210.19,120.65 212.72,120.65 220.34,113.03 220.34,109.86 219.07,109.86 IC12.13
WRITING  (via drill 0.61)  (3 unrouted)
  Top 0.254: 156.84,135.25 156.21,135.89 156.21,142.24 162.56,142.24 166.37,138.43 166.37,135.89 168.91,133.35 168.91,127 167.64,125.73 IC10.5 | 156.84,135.25 159.38,135.25 159.38,136.53 IC6.2 | v49.53,50.16 49.53,48.26 48.9,47.62 v48.9,11.43 48.9,5.08 24.77,5.08 22.86,6.99 SV1.9 | v82.55,12.06 82.55,12.7 83.82,13.97 IC41.14 | 156.84,135.25 156.21,134.62 156.21,129.54 153.67,127 v153.67,124.46 | v110.49,128.27 107.95,125.73 107.95,123.19 106.05,121.28 97.79,121.28 97.79,106.05 100.33,103.5 100.33,90.17 97.79,87.63 v97.79,76.83 | v87.63,76.2 87.63,18.41 86.36,17.14 IC41.13 | IC43.24 259.08,27.3 257.81,28.57 257.81,31.75 259.08,33.02 IC42.24 259.08,52.7 257.81,53.98 257.81,57.78 258.44,58.42 RF08A.18 | IC45.24 259.08,87.63 257.81,88.9 257.81,98.42 258.44,99.06 258.44,111.12 IC39.24 259.08,113.03 257.81,114.3 257.81,122.56 259.08,123.83 RF08B.18 | v135.89,161.93 135.89,167.64 132.08,171.45 IC50.11 | v210.19,162.56 210.82,163.19 v210.82,166.37 | v252.73,166.37 252.73,153.03 254,151.76 SV3.9
  Bottom 0.254: IC41.14 84.45,14.61 85.72,14.61 IC41.13 | v49.53,50.16 48.9,50.8 RS08.18 | v82.55,12.06 81.92,11.43 v48.9,11.43 | v153.67,124.46 152.4,123.19 146.05,123.19 145.41,122.56 136.53,122.56 135.89,123.19 135.89,126.36 133.99,126.36 132.08,128.27 v110.49,128.27 | v97.79,76.83 97.16,76.2 v87.63,76.2 | v135.89,161.93 136.53,162.56 v210.19,162.56 | v210.82,166.37 v252.73,166.37

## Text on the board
Bottom: RF08 Debug | VRS | VRS | RS08 | VRS | RS08 | RF08 | VRS
tPlace: RF08 | VRS
tValues: RF08 Debug | VRS | RS08 | VRS | RS08 | VRS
